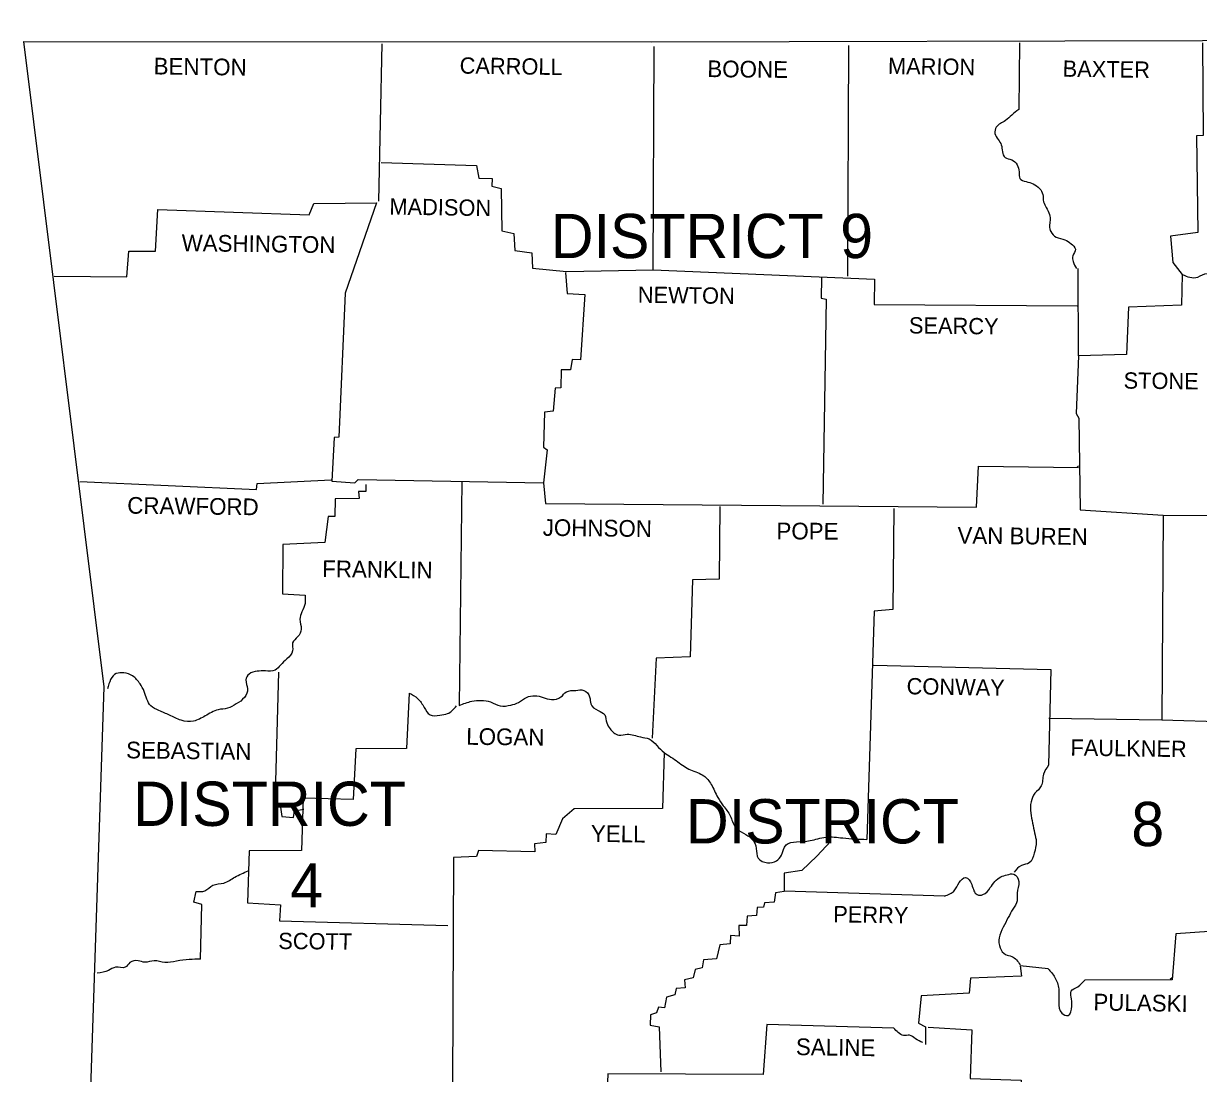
# Model space of a CAD drawing. Extents: x -33639 to 34530, y -17264 to 5867.
# Drawn here: x 1332 to 2998, y 4379 to 5867 of the extents above; entities that cross this region are included whole.
import ezdxf

# ---------------------------------------------------------------- set-up
doc = ezdxf.new("R2010")
doc.units = 0
for name, color, linetype in [('1', 7, 'Continuous'), ('2', 7, 'Continuous'), ('3', 7, 'Continuous')]:
    doc.layers.add(name, color=color, linetype=linetype)

msp = doc.modelspace()

# ---------------------------------------------------------------- linework, layer by layer
at = {"layer": '1'}
for points in [[(1332.2, 5841.4), (2222.1, 5840.9), (3003, 5842.5), (3924.3, 5856.8), (4351.4, 5866.7)], [(1332.2, 5841.4), (1446.1, 4926.7), (1396.6, 3433.6)], [(1840.1, 5838.1), (1835.2, 5615.2)], [(1839, 5669.7), (1974.4, 5665.3), (1977.7, 5647.7), (1996.4, 5647.2), (1995.9, 5636.1), (2009.1, 5632.8), (2010.2, 5572.9), (2027.3, 5569), (2028.4, 5545.3), (2052.6, 5542), (2053.7, 5520), (2101.6, 5515.1), (2224.8, 5517.8), (2225.9, 5834.3)], [(2501.7, 5835.4), (2500, 5508.5)], [(2743.8, 5839.2), (2742.7, 5745.1)], [(3003, 5839.2), (3004.1, 5708.2), (2994.8, 5707.7), (2996.4, 5570.7), (2957.9, 5565.2), (2961.2, 5528.3), (2974.4, 5511.2), (2973.3, 5467.7), (2898.5, 5465), (2895.7, 5397.8), (2827.5, 5395.6), (2824.2, 5314.2), (2828, 5307.6), (2829.7, 5177.7), (2947.5, 5170), (2945.8, 4880), (3039.4, 4877.2), (3039.4, 4582.2), (2965.6, 4576.7), (2960.1, 4511.8), (2836.3, 4511.2)], [(1375.6, 5508.5), (1478.6, 5507.9), (1481.3, 5544.2), (1519.3, 5544.2), (1522.6, 5603.1), (1737.2, 5595.4), (1743.8, 5611.9), (1832.4, 5612.5), (1787.9, 5484.8), (1779.1, 5280.6), (1772.4, 5280.1), (1769.1, 5218.4), (1801.6, 5215.7), (1806.6, 5220.6), (2069.1, 5215.7), (2071.8, 5186.5)], [(2100.5, 5514), (2102.7, 5484.3), (2128, 5482.6), (2121.4, 5390.1), (2109.8, 5390.7), (2107.6, 5375.8), (2094.4, 5375.8), (2093.9, 5350.5), (2085.6, 5350), (2082.8, 5317.5), (2070.7, 5315.8), (2069.1, 5266.3), (2074.6, 5262.5), (2069.1, 5215.7)], [(2224.8, 5517.8), (2538.5, 5504.6), (2538, 5468.8), (2825.8, 5466.6)], [(2827.5, 5395.6), (2826.9, 5519.5)], [(2463.1, 5506.3), (2462.6, 5477.6), (2469.7, 5476), (2465.3, 5185.4)], [(2071.8, 5186.5), (2682.7, 5181.6), (2685.5, 5239.3), (2827.5, 5237.7)], [(2825.8, 5238.2), (2827.5, 5239.9)], [(1412, 5217.9), (1662.4, 5206.3), (1663.5, 5215.1), (1768, 5220.1)], [(1817.6, 5213.5), (1817.6, 5203.6), (1807.1, 5203.6), (1807.7, 5193.7), (1774.1, 5193.1), (1773.5, 5168.3), (1764.2, 5168.3), (1759.2, 5131.5), (1699.8, 5128.7), (1699.3, 5058.8), (1731.2, 5056.6)], [(1953.5, 5217.9), (1949.7, 4900.3)], [(2318.9, 5182.1), (2318.4, 5079.2), (2280.4, 5078.6), (2277.1, 4969.1), (2228.7, 4967.5), (2223.2, 4854.1)], [(2565.5, 5179.4), (2564.4, 5036.3), (2538, 5034.1), (2527.5, 4710.5)], [(2947.5, 5170), (3230.3, 5168.3), (3254.6, 5179.9), (3252.9, 4964.7), (3236.4, 4957.6), (3221.5, 4944.9), (3216.6, 4940), (3216, 4878.3), (3036.1, 4878.3)], [(1693.7, 4947.7), (1688.2, 4758.3), (1696.5, 4756.1), (1698.1, 4742.9), (1714.7, 4741.8), (1716.3, 4751.2), (1729.5, 4753.4)], [(2536.9, 4957.6), (2788.4, 4951.5), (2785.1, 4815.6)], [(1878.7, 4917.9), (1874.8, 4839.2), (1803.3, 4838.7), (1799.4, 4767.1), (1728.4, 4768.8), (1726.2, 4695), (1651.9, 4694.5), (1649.7, 4620.7), (1696.5, 4618), (1694.8, 4595.4), (1933.7, 4588.8)], [(2785.6, 4882.2), (2945.8, 4880)], [(2240.2, 4833.7), (2238, 4754.5), (2112.6, 4753.9), (2096.1, 4739.6), (2086.7, 4717.6), (2072.9, 4718.7), (2072.4, 4706), (2056.4, 4704.4), (2057, 4692.8), (1977.2, 4695), (1974.4, 4686.2), (1941.4, 4685.1), (1940.3, 4363.2)], [(2476.3, 4708.3), (2456.5, 4686.8), (2435.1, 4666.4), (2410.3, 4662.6), (2410.3, 4636.7), (2398.2, 4635.1), (2396, 4621.8), (2382.2, 4620.7), (2381.1, 4614.7), (2371.8, 4614.1), (2371.2, 4602.6), (2358, 4602), (2356.9, 4588.8), (2345.9, 4588.8), (2346.5, 4573.4), (2334.4, 4574.5), (2333.8, 4562.4), (2318.9, 4561.3), (2314.5, 4541.5), (2295.8, 4539.8), (2294.2, 4528.8), (2284.3, 4526.1), (2281.5, 4514.5), (2268.9, 4511.8), (2270, 4500.2), (2257.3, 4499.1), (2255.1, 4490.3), (2243.6, 4487), (2240.8, 4472.1), (2232, 4472.7), (2229.2, 4465), (2221, 4462.2), (2220.4, 4447.4), (2233.1, 4445.2), (2235.3, 4381.3)], [(1583.1, 4540.9), (1584.8, 4618.5), (1573.8, 4621.8), (1577.1, 4636.7)], [(2637.6, 4630.1), (2410.9, 4637.3)], [(2784.5, 4527.2), (2744.9, 4531.6), (2746.6, 4516.7), (2674.5, 4514), (2672.3, 4492.5), (2604.6, 4488.7), (2600.7, 4450.1), (2610.6, 4445.2), (2610.6, 4419.9)], [(2957.4, 4512.3), (2960.1, 4515.1)], [(2565.5, 4443), (2385.5, 4448.5), (2380.6, 4377.5), (2160.4, 4378.6), (2159.3, 4354.9)], [(2614.5, 4444.6), (2676.1, 4440.8), (2673.9, 4372), (2746, 4369.2), (2747.1, 4309.2), (2781.2, 4306.5), (2781.2, 4296), (2813.2, 4293.8), (2814.3, 4255.3), (2886.9, 4255.3), (2889.1, 4217.3), (2956.3, 4214), (2955.7, 4142.5)]]:
    msp.add_lwpolyline(points, dxfattribs=at)
for points in [[(2742.7, 5745.1), (2732.8, 5736.9), (2724, 5729.2), (2710.8, 5719.8), (2709.1, 5711), (2713.6, 5702.2), (2718, 5695), (2719.6, 5685.1), (2723.5, 5676.9), (2732.8, 5673.6), (2740.5, 5666.4), (2743.3, 5656.5), (2744.4, 5647.2), (2753.2, 5642.8), (2763.1, 5639.5), (2772.4, 5632.8), (2776.8, 5624.6), (2777.9, 5614.1), (2781.8, 5605.9), (2786.2, 5596), (2787.3, 5587.7), (2786.2, 5579.5), (2788.4, 5571.8), (2795.6, 5564.1), (2808.2, 5560.2), (2817, 5554.7), (2823.1, 5547), (2819.2, 5537.6), (2819.8, 5529.4), (2824.7, 5519.5)], [(2974.4, 5511.2), (2996.4, 5507.4), (3009.6, 5512.3), (3019, 5498), (3024, 5487), (3032.2, 5471), (3045.4, 5466.1), (3055.3, 5457.3), (3055.3, 5447.9), (3046.5, 5439.1), (3039.9, 5430.3), (3042.1, 5419.9), (3044.3, 5405.5), (3044.3, 5391.8), (3041, 5379.1), (3038.3, 5367.6), (3041, 5357.7), (3051.5, 5359.3), (3062.5, 5367.6), (3074, 5367.6), (3085, 5361.5), (3096.6, 5351.1), (3108.2, 5353.3), (3117.5, 5356), (3130.7, 5359.9), (3140.1, 5354.9), (3148.3, 5348.3), (3158.2, 5337.9), (3167.6, 5331.3), (3179.7, 5325.2), (3194.6, 5321.3), (3208.3, 5312), (3210.5, 5296), (3210, 5282.3), (3208.9, 5265.2), (3207.8, 5246.5), (3209.4, 5228.3), (3215.5, 5216.2), (3223.2, 5201.9), (3225.4, 5188.7), (3224.8, 5167.8)], [(1731.2, 5056.6), (1731.2, 5045.1), (1726.8, 5033), (1724, 5022.5), (1725.7, 5008.7), (1720.7, 4997.7), (1713.6, 4988.9), (1713.6, 4977.9), (1705.3, 4966.4), (1696.5, 4957.6), (1688.8, 4950.4), (1675, 4949.3), (1663.5, 4948.8), (1651.9, 4944.9), (1647.5, 4936.6), (1649.7, 4924), (1645.3, 4911.9), (1633.8, 4902.5), (1621.1, 4896.5), (1607.9, 4894.3), (1589.7, 4885.5), (1573.2, 4878.3), (1555.6, 4879.4), (1539.1, 4886.6), (1524.2, 4893.2), (1512.7, 4899.8), (1503.3, 4920.1), (1497.3, 4931.1), (1486.8, 4942.2), (1474.2, 4946.6), (1463.7, 4945.5), (1451, 4924)], [(1878.7, 4917.9), (1890.8, 4910.2), (1900.1, 4897.6), (1908.4, 4887.1), (1922.1, 4886.6), (1933.2, 4888.8), (1945.8, 4899.8)], [(1949.7, 4900.3), (1967.8, 4906.4), (1981, 4907.5), (1994.2, 4905.3), (2008, 4899.8), (2022.9, 4900.9), (2033.9, 4904.7), (2044.9, 4911.9), (2057, 4914.1), (2068.5, 4911.9), (2080.6, 4908.6), (2093.9, 4912.4), (2101.6, 4919.6), (2114.8, 4921.8), (2126.3, 4921.8), (2134.6, 4912.4), (2136.2, 4902.5), (2146.7, 4893.2), (2156, 4887.1), (2158.8, 4875.6), (2163.7, 4867.3), (2168.7, 4861.8), (2175.9, 4858.5), (2188, 4859.6), (2206.7, 4855.7), (2218.8, 4853), (2229.8, 4843.6), (2240.2, 4833.7)], [(2240.2, 4833.7), (2259.5, 4820.5), (2277.7, 4809), (2296.4, 4800.7), (2306.8, 4788.6), (2316.2, 4769.9), (2323.9, 4758.3), (2333.8, 4744), (2341, 4728.1), (2352.5, 4719.3), (2364.6, 4711.6), (2370.7, 4697.8), (2373.4, 4684), (2386.6, 4677.4), (2399.3, 4680.2), (2406.5, 4688.4), (2413.1, 4702.7), (2427.9, 4707.2), (2447.2, 4708.8), (2469.2, 4713.8), (2493.4, 4712.7), (2527.5, 4710.5)], [(2785.1, 4815.6), (2777.9, 4802.9), (2774.6, 4786.4), (2765.8, 4775.9), (2760.3, 4763.8), (2759.8, 4747.9), (2762.5, 4733.6), (2765.3, 4719.8), (2767.5, 4707.2), (2764.7, 4691.2), (2757.6, 4677.4), (2746.6, 4673.6), (2736.1, 4664.2)], [(1577.1, 4636.7), (1589.2, 4637.8), (1600.7, 4645.5), (1616.1, 4648.8), (1631.6, 4657.1), (1650.8, 4665.9)], [(2637.6, 4630.1), (2651.4, 4637.8), (2658.5, 4649.4), (2667.3, 4656.5), (2676.1, 4646.6), (2683.8, 4632.3), (2692.1, 4632.3), (2702.5, 4642.2), (2709.1, 4651), (2717.4, 4657.6), (2726.2, 4660.4), (2735.6, 4661.5), (2742.7, 4651), (2740.5, 4634.5), (2740.5, 4623.5), (2734.5, 4611.9), (2727.9, 4599.8), (2720.7, 4586.1), (2715.2, 4571.2), (2716.3, 4556.9), (2724, 4547.5), (2732.8, 4544.8), (2744.9, 4532.7)], [(1583.1, 4540.9), (1567.2, 4540.4), (1549, 4538.2), (1532.5, 4536), (1517.6, 4538.7), (1503.9, 4536.5), (1494.5, 4538.7), (1483, 4536), (1476.4, 4529.4), (1462.6, 4529.4), (1452.7, 4525), (1436.7, 4521.1)], [(2784.5, 4527.2), (2793.9, 4515.1), (2799.4, 4498.6), (2799.4, 4479.9), (2803.8, 4464.4), (2812.6, 4461.1), (2818.1, 4474.4), (2817, 4487.6), (2817, 4495.3), (2826.4, 4501.9), (2836.3, 4511.2)], [(2606.8, 4422.6), (2596.3, 4428.1), (2588.1, 4433.1), (2579.3, 4432.5), (2572.1, 4436.9), (2565.5, 4443)]]:
    msp.add_spline(points, degree=3, dxfattribs=at)

# ---------------------------------------------------------------- texts
at = {"layer": '2'}
for s, height, rotation, p in [('BENTON', 23.67, 359.2527, (1516.5, 5794.6)), ('CARROLL', 23.11, 359.1481, (1950.2, 5795.8)), ('BOONE', 23.67, 359.4001, (2301.3, 5790.8)), ('MARION', 23.11, 359.1854, (2557.3, 5795.2)), ('BAXTER', 23.11, 359.2559, (2804.9, 5791.3)), ('MADISON', 23.11, 359.0906, (1850.6, 5596)), ('WASHINGTON', 23.66, 359.232, (1556.2, 5544.2)), ('NEWTON', 23.11, 359.2717, (2202.8, 5471)), ('SEARCY', 23.11, 359.2527, (2587, 5427.6)), ('STONE', 23.11, 359.4001, (2891.3, 5349.4)), ('CRAWFORD', 23.66, 359.2771, (1479.1, 5172.2)), ('JOHNSON', 23.67, 359.3514, (2068, 5140.8)), ('POPE', 23.67, 359.6155, (2399.3, 5135.9)), ('VAN BUREN', 23.67, 359.3508, (2655.8, 5129.8)), ('FRANKLIN', 23.67, 359.1815, (1755.4, 5082.5)), ('CONWAY', 23.11, 359.0371, (2583.7, 4916.3)), ('LOGAN', 23.67, 359.3969, (1959.6, 4844.7)), ('SEBASTIAN', 23.66, 359.2816, (1477.5, 4825.5)), ('FAULKNER', 23.11, 359.2486, (2815.9, 4829.3)), ('YELL', 23.67, 359.1987, (2136.2, 4707.2)), ('PERRY', 23.11, 359.0858, (2479.7, 4593.2)), ('SCOTT', 23.11, 359.4063, (1693.2, 4555.3)), ('PULASKI', 23.67, 359.053, (2848.4, 4468.3)), ('SALINE', 23.67, 359.1491, (2426.8, 4405))]:
    msp.add_text(s, height=height, rotation=rotation, dxfattribs=at).set_placement(p)
at = {"layer": '3'}
for s, height, p in [('DISTRICT 9', 62.74, (2079.5, 5534.3)), ('DISTRICT', 62.74, (1487.4, 4729.7)), ('DISTRICT', 62.74, (2271.1, 4704.9)), ('8', 62.7, (2902.3, 4701.1)), ('4', 62.7, (1710.3, 4614.1))]:
    msp.add_text(s, height=height, dxfattribs=at).set_placement(p)

doc.saveas('drawing.dxf')
